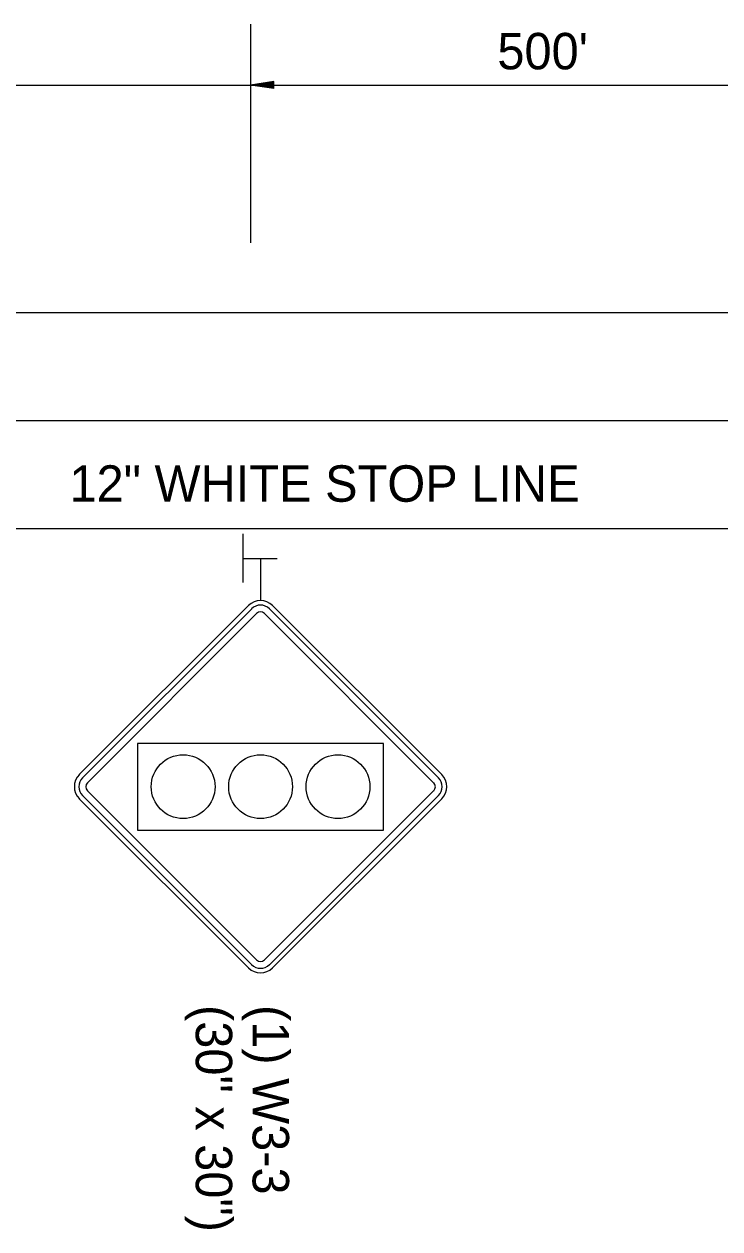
# Model space of a CAD drawing. Extents: x 1926586 to 1930787, y 596452 to 599566.
# Drawn here: x 1928434.7 to 1928549.3, y 597288.6 to 597486.9 of the extents above; entities that cross this region are included whole.
import ezdxf

# ---------------------------------------------------------------- set-up
doc = ezdxf.new("R2010")
doc.units = 0
for name, color, linetype in [('Default', 7, 'Continuous'), ('P_TC_Signs_Permanent', 7, 'Continuous'), ('R_Border', 7, 'Continuous')]:
    doc.layers.add(name, color=color, linetype=linetype)

msp = doc.modelspace()

# ---------------------------------------------------------------- linework, layer by layer
at = {"layer": 'Default'}
for p, q in [((1928471.98, 597486.95), (1928471.98, 597450.92)), ((1928373.08, 597476.91), (1928472.84, 597476.91)), ((1928475.82, 597477.48), (1928471.98, 597476.91)), ((1928471.98, 597476.91), (1928573.11, 597476.91)), ((1928475.82, 597476.33), (1928471.98, 597476.91)), ((1928475.82, 597477.39), (1928472.62, 597476.91)), ((1928475.82, 597476.43), (1928472.62, 597476.91)), ((1928475.82, 597477.29), (1928473.28, 597476.91)), ((1928475.82, 597476.53), (1928473.28, 597476.91)), ((1928475.82, 597477.19), (1928473.92, 597476.91)), ((1928475.82, 597476.62), (1928473.92, 597476.91)), ((1928475.82, 597477.1), (1928474.57, 597476.91)), ((1928475.82, 597476.72), (1928474.57, 597476.91)), ((1928475.82, 597477), (1928475.21, 597476.91)), ((1928475.82, 597476.82), (1928475.21, 597476.91)), ((1928475.82, 597476.33), (1928475.82, 597477.48)), ((1927870.1, 597439.49), (1929142.12, 597439.49)), ((1927870.1, 597421.7), (1929142.12, 597421.7)), ((1927870.1, 597403.91), (1929142.12, 597403.91)), ((1928470.8, 597395.01), (1928470.8, 597403.02)), ((1928470.92, 597398.99), (1928476.39, 597398.99))]:
    msp.add_line(p, q, dxfattribs=at)
at = {"layer": 'P_TC_Signs_Permanent'}
for p, q in [((1928443.82, 597363.39), (1928471.67, 597391.23)), ((1928475.64, 597391.23), (1928503.48, 597363.39)), ((1928444.35, 597362.86), (1928472.2, 597390.7)), ((1928472.99, 597389.9), (1928445.15, 597362.06)), ((1928502.16, 597362.06), (1928474.32, 597389.9)), ((1928475.11, 597390.7), (1928502.95, 597362.86)), ((1928472.2, 597332.1), (1928444.35, 597359.94)), ((1928445.15, 597360.74), (1928472.99, 597332.89)), ((1928474.32, 597332.89), (1928502.16, 597360.74)), ((1928502.95, 597359.94), (1928475.11, 597332.1)), ((1928471.67, 597331.57), (1928443.82, 597359.41)), ((1928503.48, 597359.41), (1928475.64, 597331.57))]:
    msp.add_line(p, q, dxfattribs=at)
msp.add_lwpolyline([(1928453.41, 597368.52), (1928453.41, 597354.27), (1928493.91, 597354.27), (1928493.91, 597368.52)], close=True, dxfattribs=at)
for centre in [(1928460.91, 597361.4), (1928473.66, 597361.4), (1928486.41, 597361.4)]:
    msp.add_circle(centre, 5.25, dxfattribs=at)
for centre, radius, start, end in [((1928473.65, 597389.24), 2.81, 45, 135), ((1928473.65, 597389.24), 2.06, 45, 135), ((1928473.65, 597389.24), 0.938, 45, 135), ((1928445.81, 597361.4), 2.81, 135, 225), ((1928445.81, 597361.4), 2.06, 135, 225), ((1928445.81, 597361.4), 0.938, 135, 225), ((1928501.5, 597361.4), 0.938, 315, 45), ((1928501.5, 597361.4), 2.06, 315, 45), ((1928501.5, 597361.4), 2.81, 315, 45), ((1928473.65, 597333.56), 2.06, 225, 315), ((1928473.65, 597333.56), 0.938, 225, 315), ((1928473.65, 597333.56), 2.81, 225, 315)]:
    msp.add_arc(centre, radius, start, end, dxfattribs=at)
at = {"layer": 'R_Border'}
msp.add_line((1928473.65, 597398.99), (1928473.65, 597392.05), dxfattribs=at)

# ---------------------------------------------------------------- texts
at = {"layer": 'Default'}
for s, p in [("500'", (1928512.65, 597479.5)), ('12" WHITE STOP LINE', (1928442.2, 597408.31))]:
    msp.add_text(s, height=6, rotation=360, dxfattribs=at).set_placement(p)
at = {"layer": 'R_Border'}
for s, height, p in [('(30" x 30")', 5.9996, (1928462.99, 597325.46)), ('(1) W3-3', 6, (1928472.35, 597325.46))]:
    msp.add_text(s, height=height, rotation=270, dxfattribs=at).set_placement(p)

doc.saveas('drawing.dxf')
